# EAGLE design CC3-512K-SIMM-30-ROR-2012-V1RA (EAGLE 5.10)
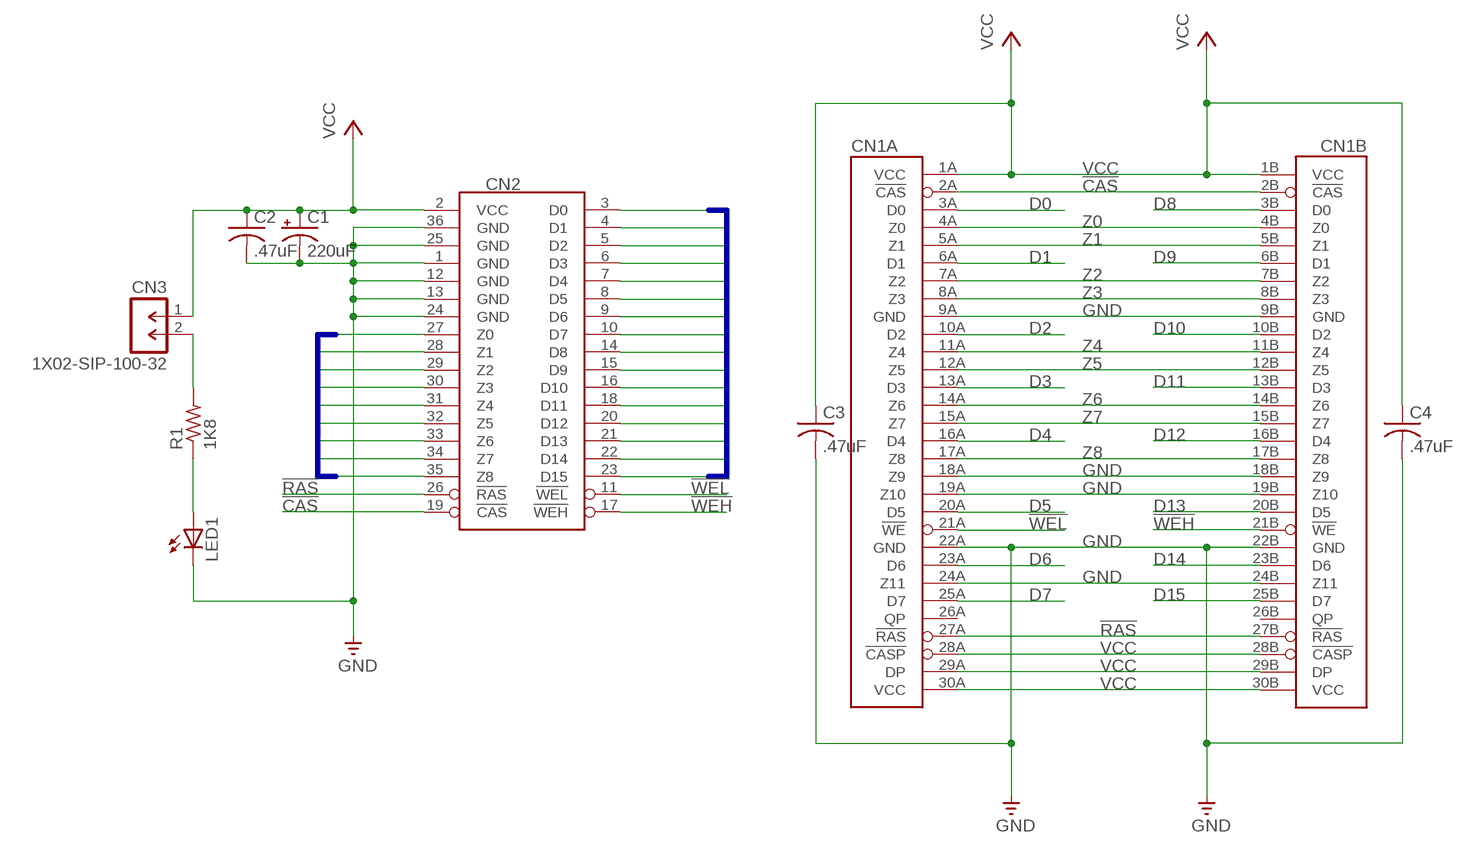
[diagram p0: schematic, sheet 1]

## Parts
C1  220uF  P-CAPACITOR-CPOL-RADIAL-1  [CPOL-RADIAL-1]
C2  .47uF  NP-CAPACITOR-C050-025X075  [C050-025X075]
C3  .47uF  NP-CAPACITOR-C050-025X075  [C050-025X075]
C4  .47uF  NP-CAPACITOR-C050-025X075  [C050-025X075]
CN1  DUAL-SIMM-30-UNIVERSAL-UNIVERSAL  [DUAL-SIMM-30-UNIVERSAL]
CN2  COCO3-MEMORY-EXPANSION-HEADER  [COCO3-MEMORY-EXPANSION-HEADER]
CN3  1X02-SIP-100-32  [SIL1X02-100]
LED1  LED5MM  [LED5MM]
R1  1K8  RESISTOR  [0207/10]

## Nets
!CAS: CN1.2A(A:!CAS) CN1.2B(B:!CAS) CN2.19(!CAS)
!RAS: CN1.27A(A:!RAS) CN1.27B(B:!RAS) CN2.26(!RAS)
!WEH: CN1.21B(B:!WE) CN2.17(!WEH)
!WEL: CN1.21A(A:!WE) CN2.11(!WEL)
D0: CN1.3A(A:D0) CN2.3(D0)
D1: CN1.6A(A:D1) CN2.4(D1)
D2: CN1.10A(A:D2) CN2.5(D2)
D3: CN1.13A(A:D3) CN2.6(D3)
D4: CN1.16A(A:D4) CN2.7(D4)
D5: CN1.20A(A:D5) CN2.8(D5)
D6: CN1.23A(A:D6) CN2.9(D6)
D7: CN1.25A(A:D7) CN2.10(D7)
D8: CN1.3B(B:D0) CN2.14(D8)
D9: CN1.6B(B:D1) CN2.15(D9)
D10: CN1.10B(B:D2) CN2.16(D10)
D11: CN1.13B(B:D3) CN2.18(D11)
D12: CN1.16B(B:D4) CN2.20(D12)
D13: CN1.20B(B:D5) CN2.21(D13)
D14: CN1.23B(B:D6) CN2.22(D14)
D15: CN1.25B(B:D7) CN2.23(D15)
GND [power]: C1.2(-) C2.2(-) C3.2(-) C4.2(-) CN1.9A(A:GND) CN1.9B(B:GND) CN1.18A(A:Z9) CN1.18B(B:Z9) CN1.19A(A:Z10) CN1.19B(B:Z10) CN1.22A(A:GND) CN1.22B(B:GND) CN1.24A(A:Z11) CN1.24B(B:Z11) CN2.1(GND) CN2.12(GND) CN2.13(GND) CN2.24(GND) CN2.25(GND) CN2.36(GND) LED1.K(C)
N$45: LED1.A R1.1
N$46: CN3.2 R1.2
VCC [power]: C1.1(+) C2.1(+) C3.1(+) C4.1(+) CN1.1A(A:VCC) CN1.1B(B:VCC) CN1.28A(A:!CASP) CN1.28B(B:!CASP) CN1.29A(A:DP) CN1.29B(B:DP) CN1.30A(A:VCC) CN1.30B(B:VCC) CN2.2(VCC) CN3.1
Z0: CN1.4A(A:Z0) CN1.4B(B:Z0) CN2.27(Z0)
Z1: CN1.5A(A:Z1) CN1.5B(B:Z1) CN2.28(Z1)
Z2: CN1.7A(A:Z2) CN1.7B(B:Z2) CN2.29(Z2)
Z3: CN1.8A(A:Z3) CN1.8B(B:Z3) CN2.30(Z3)
Z4: CN1.11A(A:Z4) CN1.11B(B:Z4) CN2.31(Z4)
Z5: CN1.12A(A:Z5) CN1.12B(B:Z5) CN2.32(Z5)
Z6: CN1.14A(A:Z6) CN1.14B(B:Z6) CN2.33(Z6)
Z7: CN1.15A(A:Z7) CN1.15B(B:Z7) CN2.34(Z7)
Z8: CN1.17A(A:Z8) CN1.17B(B:Z8) CN2.35(Z8)
Unconnected: CN1.26A(A:QP) CN1.26B(B:QP)

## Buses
D[0..15]
Z[0..8]

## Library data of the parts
C1 = GIMEchip-Capacitor:P-CAPACITOR: POLARIZED CAPACITOR
C2-C4 = GIMEchip-Capacitor:NP-CAPACITOR: NON-POLARIZED CAPACITOR
CN1 = GIMEchip-DRAM:DUAL-SIMM-30-UNIVERSAL
CN2 = GIMEchip-TRS-80-CoCo-3-Memory-Expansion-Connector:COCO3-MEMORY-EXPANSION-HEADER: Tandy Color Computer 3 Memory Expansion Connector Tandy Radio Shack TRS-80 Color Computer 3 Memory Expansion Header. CN6, CN5, CN4 on the CoCo 3 Motherboard. These connectors were intended, by Tandy, to upgrade the CoCo 3 from 128k RAM to 512k RAM. Used by third parties for expansion to: 256k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
CN3 = GIMEchip-Header-Generic:1X02: MALE HEADER
LED1 = adafruit:LED: LED
R1 = GIMEchip-Resistor:RESISTOR

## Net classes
0 default: width 0.305 mm, clearance 0.203 mm
1 power: width 0.889 mm, clearance 0.203 mm

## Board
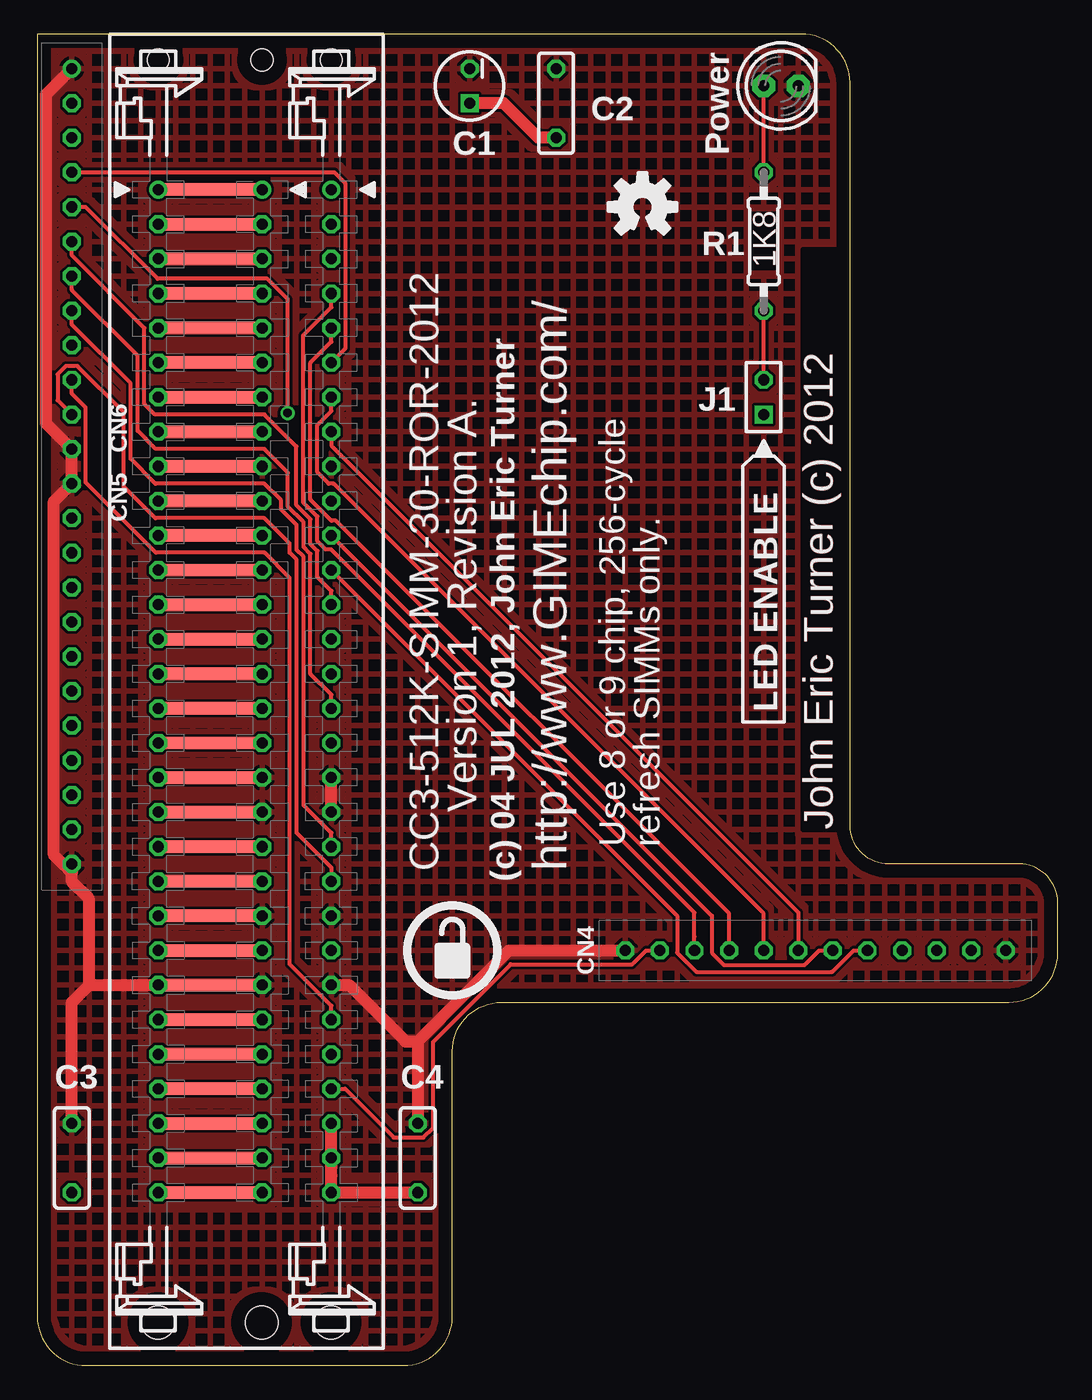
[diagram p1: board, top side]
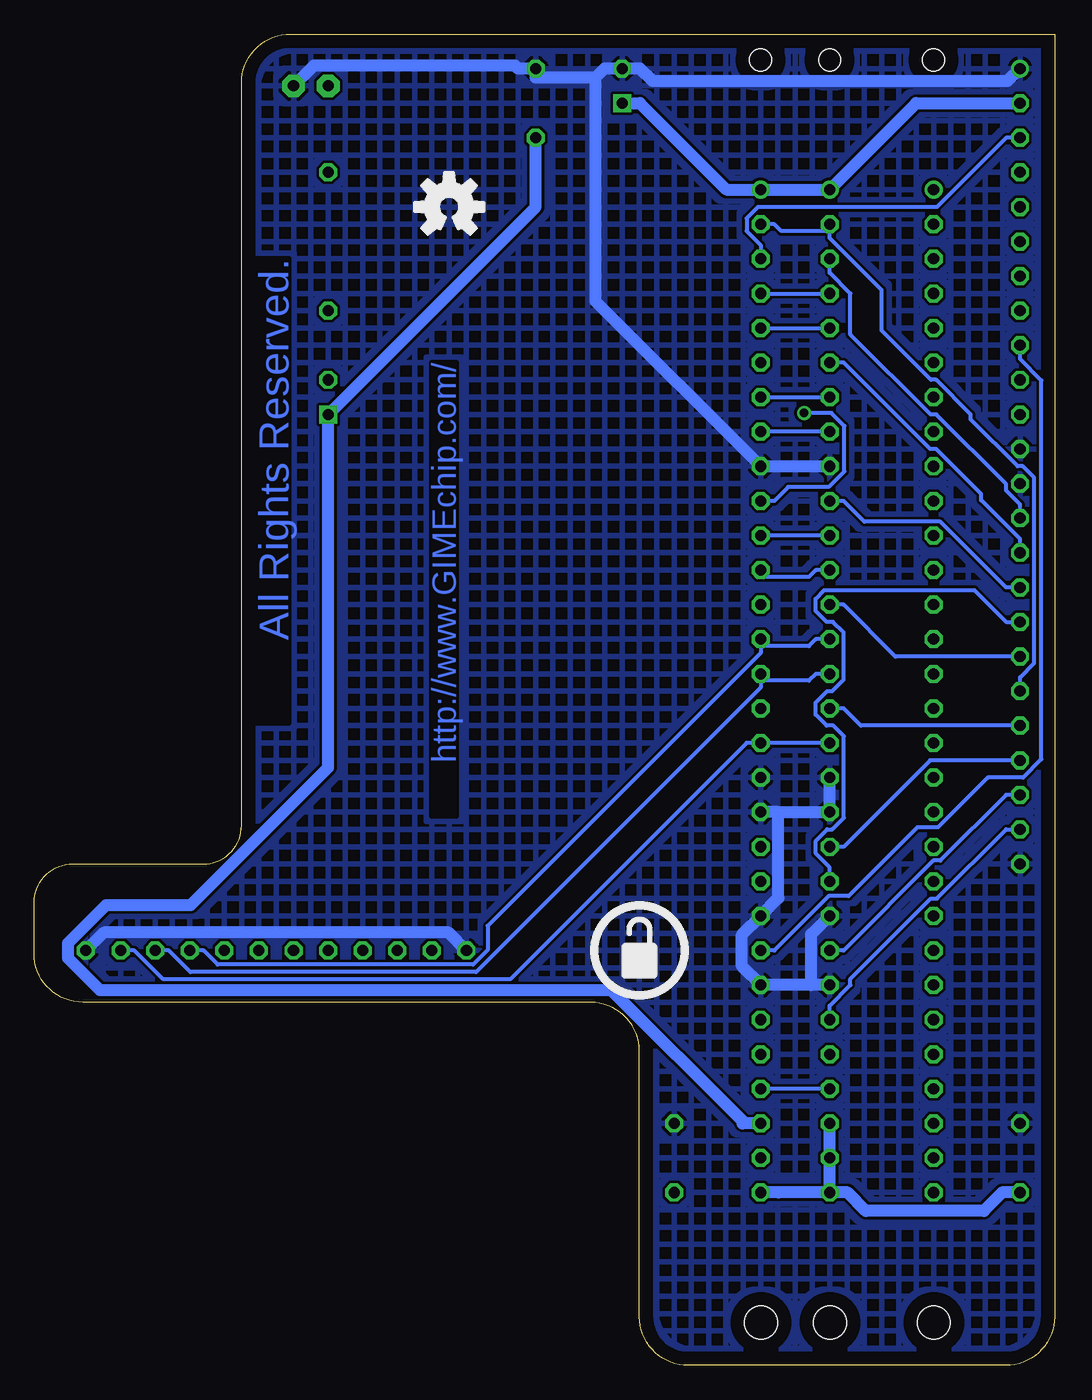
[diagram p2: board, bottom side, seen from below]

Size 74.93 x 97.79 mm. Coordinates in mm from the lower left corner, seen from the top.
Outline: 0,97.79 0,3.59 arc90 3.59,0 26.89,0 arc90 30.48,3.59 30.48,23.08 arc-90 34.07,26.67 71.34,26.67 arc90 74.93,30.26 74.93,33.99 arc90 72.09,36.83 67.31,36.83 62.53,36.83 arc-90 59.69,39.67 59.69,94.2 arc90 56.1,97.79 0,97.79
Copper layers (1*16): Top 0.035mm / dielectric 1.5mm / Bottom 0.035mm
Design rules "default": minimum track width 10mil, minimum drill 24mil, track to track 8mil, track to pad 8mil, pad to pad 8mil, via to via 8mil, smd to smd 8mil, copper to edge 40mil, drill to drill 8mil, minimum pad ring 10mil, minimum via ring 8mil, stop-mask expansion 4mil, vias tented up to drill 0mil, thermal gap 10mil
vRestrict: area 26.7,34.3 to 52.1,87.6

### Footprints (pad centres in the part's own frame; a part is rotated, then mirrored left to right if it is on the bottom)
CPOL-RADIAL-1 = drill 0.813 square: 1 1.27,0 | drill 0.813 octagon: 2 -1.27,0
C050-025X075 = drill 0.813 octagon: 1 -2.54,0; 2 2.54,0
DUAL-SIMM-30-UNIVERSAL = drill 0.813 round: 1 -36.83,-3.81; 1A -36.83,8.89; 1B -36.83,3.81 | drill 0.813 octagon: 2 -34.29,-3.81; 2A -34.29,8.89; 2B -34.29,3.81; 3 -31.75,-3.81; 3A -31.75,8.89; 3B -31.75,3.81; 4 -29.21,-3.81; 4A -29.21,8.89; 4B -29.21,3.81; 5 -26.67,-3.81; 5A -26.67,8.89; 5B -26.67,3.81; 6 -24.13,-3.81; 6A -24.13,8.89; 6B -24.13,3.81; 7 -21.59,-3.81; 7A -21.59,8.89; 7B -21.59,3.81; 8 -19.05,-3.81; 8A -19.05,8.89; 8B -19.05,3.81; 9 -16.51,-3.81; 9A -16.51,8.89; 9B -16.51,3.81; 10 -13.97,-3.81; 10A -13.97,8.89; 10B -13.97,3.81; 11 -11.43,-3.81; 11A -11.43,8.89; 11B -11.43,3.81; 12 -8.89,-3.81; 12A -8.89,8.89; 12B -8.89,3.81; 13 -6.35,-3.81; 13A -6.35,8.89; 13B -6.35,3.81; 14 -3.81,-3.81; 14A -3.81,8.89; 14B -3.81,3.81; 15 -1.27,-3.81; 15A -1.27,8.89; 15B -1.27,3.81; 16 1.27,-3.81; 16A 1.27,8.89; 16B 1.27,3.81; 17 3.81,-3.81; 17A 3.81,8.89; 17B 3.81,3.81; 18 6.35,-3.81; 18A 6.35,8.89; 18B 6.35,3.81; 19 8.89,-3.81; 19A 8.89,8.89; 19B 8.89,3.81; 20 11.43,-3.81; 20A 11.43,8.89; 20B 11.43,3.81; 21 13.97,-3.81; 21A 13.97,8.89; 21B 13.97,3.81; 22 16.51,-3.81; 22A 16.51,8.89; 22B 16.51,3.81; 23 19.05,-3.81; 23A 19.05,8.89; 23B 19.05,3.81; 24 21.59,-3.81; 24A 21.59,8.89; 24B 21.59,3.81; 25 24.13,-3.81; 25A 24.13,8.89; 25B 24.13,3.81; 26 26.67,-3.81; 26A 26.67,8.89; 26B 26.67,3.81; 27 29.21,-3.81; 27A 29.21,8.89; 27B 29.21,3.81; 28 31.75,-3.81; 28A 31.75,8.89; 28B 31.75,3.81; 29 34.29,-3.81; 29A 34.29,8.89; 29B 34.29,3.81; 30 36.83,-3.81; 30A 36.83,8.89; 30B 36.83,3.81 | smd 0.914 x 7.62: P$1 -36.83,0; P$2 -34.29,0; P$3 -31.75,0; P$4 -29.21,0; P$5 -26.67,0; P$6 -24.13,0; P$7 -21.59,0; P$8 -19.05,0; P$9 -16.51,0; P$10 -13.97,0; P$11 -11.43,0; P$12 -8.89,0; P$13 -6.35,0; P$14 -3.81,0; P$15 -1.27,0; P$16 1.27,0; P$17 3.81,0; P$18 6.35,0; P$19 8.89,0; P$20 11.43,0; P$21 13.97,0; P$22 16.51,0; P$23 19.05,0; P$24 21.59,0; P$25 24.13,0; P$26 26.67,0; P$27 29.21,0; P$28 31.75,0; P$29 34.29,0; P$30 36.83,0 | hole 2.413: 46.38,-3.835; 46.38,8.865; 46.38,3.785 | hole 1.6: -46.355,-3.81; -46.355,8.89; -46.355,3.81
COCO3-MEMORY-EXPANSION-HEADER = drill 0.813 round: 1 -2.54,30.48 | drill 0.813 octagon: 2 -2.54,27.94; 3 -2.54,25.4; 4 -2.54,22.86; 5 -2.54,20.32; 6 -2.54,17.78; 7 -2.54,15.24; 8 -2.54,12.7; 9 -2.54,10.16; 10 -2.54,7.62; 11 -2.54,5.08; 12 -2.54,2.54; 13 -2.54,0; 14 -2.54,-2.54; 15 -2.54,-5.08; 16 -2.54,-7.62; 17 -2.54,-10.16; 18 -2.54,-12.7; 19 -2.54,-15.24; 20 -2.54,-17.78; 21 -2.54,-20.32; 22 -2.54,-22.86; 23 -2.54,-25.4; 24 -2.54,-27.94; 25 38.1,-34.29; 26 40.64,-34.29; 27 43.18,-34.29; 28 45.72,-34.29; 29 48.26,-34.29; 30 50.8,-34.29; 31 53.34,-34.29; 32 55.88,-34.29; 33 58.42,-34.29; 34 60.96,-34.29; 35 63.5,-34.29; 36 66.04,-34.29
SIL1X02-100 = drill 0.813 square: 1 -1.27,0 | drill 0.813 octagon: 2 1.27,0
LED5MM = drill 0.813 pad 1.676 octagon: A -1.27,0; K 1.27,0
0207/10 = drill 0.813 octagon: 1 -5.08,0; 2 5.08,0

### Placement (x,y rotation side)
C1  31.75,93.98 270 top
C2  38.1,92.71 90 top
C3  2.54,15.24 90 top
C4  27.94,15.24 90 top
CN1  12.7,49.53 270 top
CN2  5.08,64.77 0 top
CN3  53.34,71.12 90 top
LED1  54.61,93.98 0 top
R1  53.34,82.55 270 top
U$1  [OSHWLOGO_0.3]  30.48,30.48 0 top
U$2  [OSHWLOGO_0.3]  30.48,30.48 0 bottom
U$3  [OSHWLOGO_TOL_0.2]  44.45,85.09 0 top
U$4  [OSHWLOGO_TOL_0.2]  44.45,85.09 0 bottom

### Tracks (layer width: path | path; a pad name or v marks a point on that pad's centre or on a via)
!CAS
  Bottom 0.305: CN1.2A 20.57,83.82 20.07,83.31 16.51,83.31 | 16.51,83.31 16.51,82.8 12.7,78.99 12.7,76.01 9.08,72.39 8.71,72.39 6.17,69.85 6.17,69.49 2.72,66.04 2.34,66.04 1.5,65.2 1.5,51.58 2.54,50.55 CN2.19 | 16.51,83.31 CN1.2B
!RAS
  Top 0.305: CN1.27A 22.61,20.32 26.17,16.75 28.35,16.75 29.06,17.46 29.06,23.76 34.76,29.46 43.69,29.46 44.7,30.48 CN2.26
  Bottom 0.305: CN1.27B CN1.27A
!WEH
  Bottom 0.305: CN1.21B 16.51,36.58 17.53,37.6 17.53,38.53 16.7,39.37 16.34,39.37 15.48,40.23 15.48,46.22 16.25,46.99 16.74,46.99 17.55,47.8 17.55,48.69 16.71,49.53 16.34,49.53 15.49,50.37 15.49,53.83 16.27,54.61 16.74,54.61 17.55,55.42 17.55,56.31 16.92,56.94 5.88,56.94 3.56,54.61 CN2.17
!WEL
  Top 0.305: CN2.11 1.5,70.89 1.5,72.8 2.11,73.41 2.95,73.41 6.35,70.02 6.35,64.55 8.67,62.23 16.69,62.23 18.54,60.38 18.54,59.7 19.05,59.19 19.05,39.12 21.59,36.58 CN1.21A
D0
  Bottom 0.305: CN1.3A 21.59,82.3 22.61,83.32 22.61,84.26 21.78,85.09 8.64,85.09 3.56,90.17 CN2.3
D1
  Top 0.305: CN2.4 21.81,87.63 22.62,86.82 22.62,74.69 CN1.6A
D2  (via drill 0.61 pad 1.02)
  Top 0.305: CN2.5 3.56,85.09 8.83,79.81 16.89,79.81 18.39,78.32 v18.39,69.96
  Bottom 0.305: CN1.10A 20.57,63.5 19.56,64.52 16.58,64.52 15.44,65.66 15.44,69.01 16.39,69.96 v18.39,69.96
D3
  Top 0.305: CN2.6 2.54,81.53 7.87,76.2 7.87,70.61 8.64,69.85 16.69,69.85 19.04,67.5 19.04,63.18 20.07,62.15 20.07,60.33 20.57,59.82 20.57,57.91 21.59,56.9 CN1.13A
D4
  Top 0.305: CN2.7 2.54,78.99 7.37,74.17 7.37,68.66 8.71,67.31 16.68,67.31 18.41,65.58 18.41,63.08 19.56,61.94 19.56,60.12 20.07,59.61 20.07,50.8 21.59,49.28 CN1.16A
D5
  Top 0.305: CN2.8 2.54,76.45 6.86,72.14 6.86,66.6 8.68,64.77 16.68,64.77 17.91,63.55 17.91,62.87 19.05,61.73 19.05,59.91 19.56,59.4 19.56,41.15 21.59,39.12 CN1.20A
D6
  Bottom 0.305: CN2.9 2.54,73.91 0.97,72.34 0.97,44.53 2.32,43.18 4.9,43.18 8.57,39.52 10.07,39.52 15.12,34.47 16.58,34.47 20.57,30.48 CN1.23A
D7
  Top 0.305: CN1.25A 21.59,26.42 18.54,29.46 18.54,57.85 16.7,59.69 8.72,59.69 3.56,64.85 3.56,70.36 2.54,71.37 CN2.10
D8
  Bottom 0.305: CN1.3B 16.51,80.26 14.99,78.74 14.99,75.73 9.11,69.85 8.67,69.85 3.56,64.73 3.56,64.26 2.54,63.25 CN2.14
D9
  Bottom 0.305: CN1.6B 15.49,73.66 9.14,67.31 8.69,67.31 5.39,64.01 5.39,63.56 2.54,60.71 CN2.15
D10
  Bottom 0.305: CN1.10B 15.49,63.5 13.97,61.98 8.38,61.98 3.56,57.15 CN2.16
D11
  Bottom 0.305: CN1.13B 15.49,55.88 11.68,52.07 CN2.18
D12
  Bottom 0.305: CN1.16B 15.49,48.26 14.22,46.99 CN2.20
D13
  Bottom 0.305: CN1.20B 15.49,38.1 9.14,44.45 CN2.21
D14
  Bottom 0.305: CN1.23B 15.49,30.48 8.9,37.08 8.39,37.08 3.56,41.91 CN2.22
D15
  Bottom 0.305: CN1.25B 16.51,26.42 14.99,27.94 14.99,28.4 9.09,34.29 8.64,34.29 3.56,39.37 CN2.23
GND
  Top 0.889: CN1.24A 22.9,27.94 27.05,23.79 27.94,23.79 | 27.94,23.79 C4.2 | CN2.25 34.63,30.48 27.94,23.79 | CN2.1 0.66,93.37 0.66,69.19 CN2.12 CN2.13 1.23,63.46 1.23,37.49 2.54,36.18 | 2.54,36.18 2.54,35.52 3.81,34.25 3.81,27.94 | 2.54,36.18 CN2.24 | CN1.19A CN1.18A | 3.81,27.94 CN1.24B | C3.2 2.54,26.67 3.81,27.94
  Bottom 0.889: 20.28,40.64 CN1.19B 16.51,41.87 CN1.18B | CN2.25 44.49,31.79 69.81,31.79 CN2.36 | 20.28,40.64 20.28,34.33 CN1.22A 22.96,31.64 22.96,29.32 CN1.24A 17.87,27.94 | 20.28,40.64 CN1.19A | 33.71,94.6 33.06,95.25 C1.2 30.44,95.25 29.52,94.33 3.46,94.33 CN2.1 | 33.71,94.6 38.1,94.6 C2.2 39.41,95.25 39.63,95.47 54.39,95.47 LED1.K | 33.71,94.6 33.71,78.16 CN1.9A 17.82,66.04 CN1.9B | CN1.24B 17.87,27.94 | 17.87,27.94 17.87,31.66 CN1.22B
  pour Bottom (hatched): 0,97.79 59.69,97.79 59.69,36.83 74.93,36.83 74.93,26.67 30.48,26.67 30.48,0 0,0
  pour Top (hatched): 0,97.79 59.69,97.79 59.69,36.83 74.93,36.83 74.93,26.67 30.48,26.67 30.48,0 0,0
N$45
  Top 0.305: R1.1 LED1.A
N$46
  Top 0.305: CN3.2 R1.2
VCC
  Top 0.889: C2.1 36.79,90.17 34.25,92.71 C1.1 | C4.1 26.63,12.7 CN1.30A 21.59,13.93 21.59,14.59 CN1.29A CN1.28A
  Bottom 0.889: CN1.28A 22.9,17.78 22.9,17.92 32.54,27.56 70.07,27.56 72.43,29.91 72.43,31.02 69.65,33.81 63.44,33.81 53.34,43.91 CN3.1 38.1,85.09 C2.1 | C1.1 30.44,92.71 24.09,86.36 CN1.1A CN1.1B 10.16,92.71 CN2.2 | C3.1 3.85,12.7 5.19,11.36 13.86,11.36 15.2,12.7 CN1.30B | CN1.30B 20.28,12.7 CN1.30A | CN1.30B CN1.29B CN1.28B
Z0
  Top 0.305: CN2.27 48.26,31.5 | 48.26,31.5 48.26,33.26 21.58,59.94 21.17,59.94 20.57,60.54 20.57,62.36 19.55,63.39 19.55,75.68 21.59,77.72 CN1.4A | 48.26,31.5
  Bottom 0.305: CN1.4A CN1.4B
Z1
  Top 0.305: CN1.5A 21.59,75.18 20.05,73.65 20.05,63.6 21.6,62.05 | CN2.28 50.8,33.19 21.94,62.05 21.6,62.05 | 21.6,62.05
  Bottom 0.305: CN1.5A CN1.5B
Z2
  Top 0.305: CN1.7A 21.59,70.1 20.56,69.08 20.56,65.6 21.39,64.77 21.77,64.77 53.34,33.2 CN2.29
  Bottom 0.305: CN1.7A CN1.7B
Z3
  Top 0.305: CN2.30 55.88,33.27 21.59,67.56 CN1.8A
  Bottom 0.305: CN1.8B CN1.8A
Z4
  Top 0.305: CN2.31 57.4,30.48 56.34,29.42 50.41,29.42 49.53,30.3 49.53,33.02 CN1.11A
  Bottom 0.305: CN1.11B CN1.11A
Z5
  Top 0.305: CN1.12A 46.99,33.02 46.99,30.3 48.39,28.91 58.37,28.91 59.94,30.48 CN2.32
  Bottom 0.305: CN1.12B 17.53,58.42 18.03,57.91 21.59,57.91 CN1.12A
Z6
  Bottom 0.305: CN1.14B 17.53,53.34 18.03,52.83 21.59,52.83 | 21.59,52.83 21.59,52.32 41.63,32.29 41.63,30.52 42.69,29.45 61.46,29.45 62.48,30.48 CN2.33 | 21.59,52.83 CN1.14A
Z7
  Bottom 0.305: CN1.15B 17.53,50.8 18.03,50.29 21.59,50.29 | 21.59,50.29 21.59,49.78 42.47,28.9 63.45,28.9 65.02,30.48 CN2.34 | 21.59,50.29 CN1.15A
Z8
  Bottom 0.305: CN1.17B CN1.17A 22.61,45.72 39.97,28.36 65.44,28.36 67.56,30.48 CN2.35

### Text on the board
Top: 1K8 | John Eric Turner (c) 2012
Bottom: All Rights Reserved. | http://www.GIMEchip.com/
tPlace: Use 8 or 9 chip, 256-cycle | refresh SIMMs only.
tNames: CN1 | C2 | 220uF | 1X02-SIP-100-32 | C1 | Power | 1K8 | C1 | CN3 | R1 | R1 | CN2 | LED1 | C2 | 1K8 | .47uF | J1 | CN6 | CN5 | LED ENABLE | Version 1, Revision A. | John Eric Turner (c) 2012 | CC3-512K-SIMM-30-ROR-2012 | http://www.GIMEchip.com/ | (c) 04 JUL 2012, John Eric Turner | CN4 | C3 | C4 | C3 | C4 | .47uF | .47uF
